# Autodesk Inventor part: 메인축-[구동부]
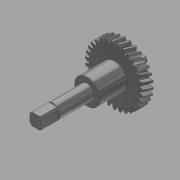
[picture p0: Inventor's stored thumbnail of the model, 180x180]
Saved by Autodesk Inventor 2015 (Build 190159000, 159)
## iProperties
Created: 2017-11
Part Number: 메인축-[구동부]
Material: 강철, 탄소
Document SubType Name: Modeling
Designer: mduedu
Categories: <?xml version="1.0" encoding="UTF-16"?> <MemberInstance><Categories><FamilyTemplate><FamilyTemplateParameter ValueType="xs:double" Id="1" ObjectReferenceKey="da
Density: 7.87 g/cm^3
Mass: 607.365 g
Surface Area: 183.17 cm^2
Volume: 77.1747 cm^3
Appearance: 반광택
CustomPartVersion: 1
Author: mduedu
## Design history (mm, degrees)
sketch "Sketch1"
  geometry: C1 r 34.094 at (0, 0)
  constraints: 1 centre point
  dimensions: "d0" = 68.18712 diameter of C1 (= da_da)
extrude "Extrusion1" new body sketch "Sketch1" distance "d1" = 12 (= da_b); taper "d2" = 0 deg
workplane "Work Plane2"
sketch "Sketch2"
  geometry: C1 r 34.094 at (0, 0) reference; C2 r 32.094 at (0, 0)
  constraints: 1 centre point, 1 coincident
  dimensions: "d3" = 64.18712 diameter of C2 (= da_dw)
feature "피치 지름" sketch "Sketch2" dims "d4" = 10, "d5" = 0
workplane "Work Plane8"
workplane "Work Plane9"
feature "스퍼 기어" dims "da_b" = 12, "da_d" = 64.18712, "da_aw" = 54.86964, "da_da" = 68.18712, "da_df" = 59.18712, "da_dw" = 64.18712, angle "da_beta" = 15 deg, "da_lefttooth" = 0, "da_righttooth" = 10
sketch "스케치3"
  geometry: C1 r 15 at (0, 0); 1 further point
  constraints: 1 centre point, 1 coincident
  dimensions: "d49" = 30 diameter of C1
extrude "돌출2" join sketch "스케치3" distance "d50" = 32; taper "d51" = 0 deg
sketch "스케치4"
  geometry: C1 r 8.5 at (0, 0); 1 further point
  constraints: 1 centre point, 1 coincident
  dimensions: "d52" = 17 diameter of C1
extrude "돌출3" join sketch "스케치4" distance "d53" = 60; taper "d54" = 0 deg
sketch "스케치5"
  geometry: C1 r 7.5 at (0, 0); 1 further point
  constraints: 1 centre point, 1 coincident
  dimensions: "d55" = 15 diameter of C1
extrude "돌출4" join sketch "스케치5" distance "d56" = 16; taper "d57" = 0 deg
sketch "스케치6"
  geometry: C1 r 4 at (0, 0); 1 further point
  constraints: 1 centre point, 1 coincident
  dimensions: "d58" = 8 diameter of C1
extrude "돌출5" join sketch "스케치6" distance "d59" = 7; taper "d60" = 0 deg
chamfer "모따기1" distance "d61" = 0.5; stored, may be unused: second distance "d62" = 2, angle "d63" = 45 deg
fillet "모깎기1" dims "d64" = 0.5
sketch "스케치7"
  geometry: L1 (-7, -7)-(7, -7); L2 (7, -7)-(7, 7); L3 (7, 7)-(-7, 7); L4 (-7, 7)-(-7, -7); L5 (-7, -7)-(7, 7); L6 (7, -7)-(-7, 7); L7 (-10, -10)-(10, -10); L8 (10, -10)-(10, 10); L9 (10, 10)-(-10, 10); L10 (-10, 10)-(-10, -10); L11 (-10, -10)-(10, 10); L12 (10, -10)-(-10, 10); 1 further point
  constraints: 24 end point, 4 midpoint, 4 parallel, 2 horizontal, 2 perpendicular
  dimensions: "d65" = 14 distance of L3.end L2.end; "d66" = 14 distance of L2.end L1.end; "d67" = 20 distance of L9.end L8.end; "d68" = 20 distance of L8.end L7.end
extrude "돌출6" cut sketch "스케치7" distance "d69" = 20; taper "d70" = 0 deg
body "Solid1"
body "Srf1"
other parameters: "d16" = 54.86964 (= da_aw), "d17" = 0, "d34" = 1.01342 (computed from da_z), "d39" = 0, "d41" = 0, "d43" = 54.86964 (= da_aw), "d46" = 54.86964 (= da_aw), "d47" = 0, "d48" = 0
